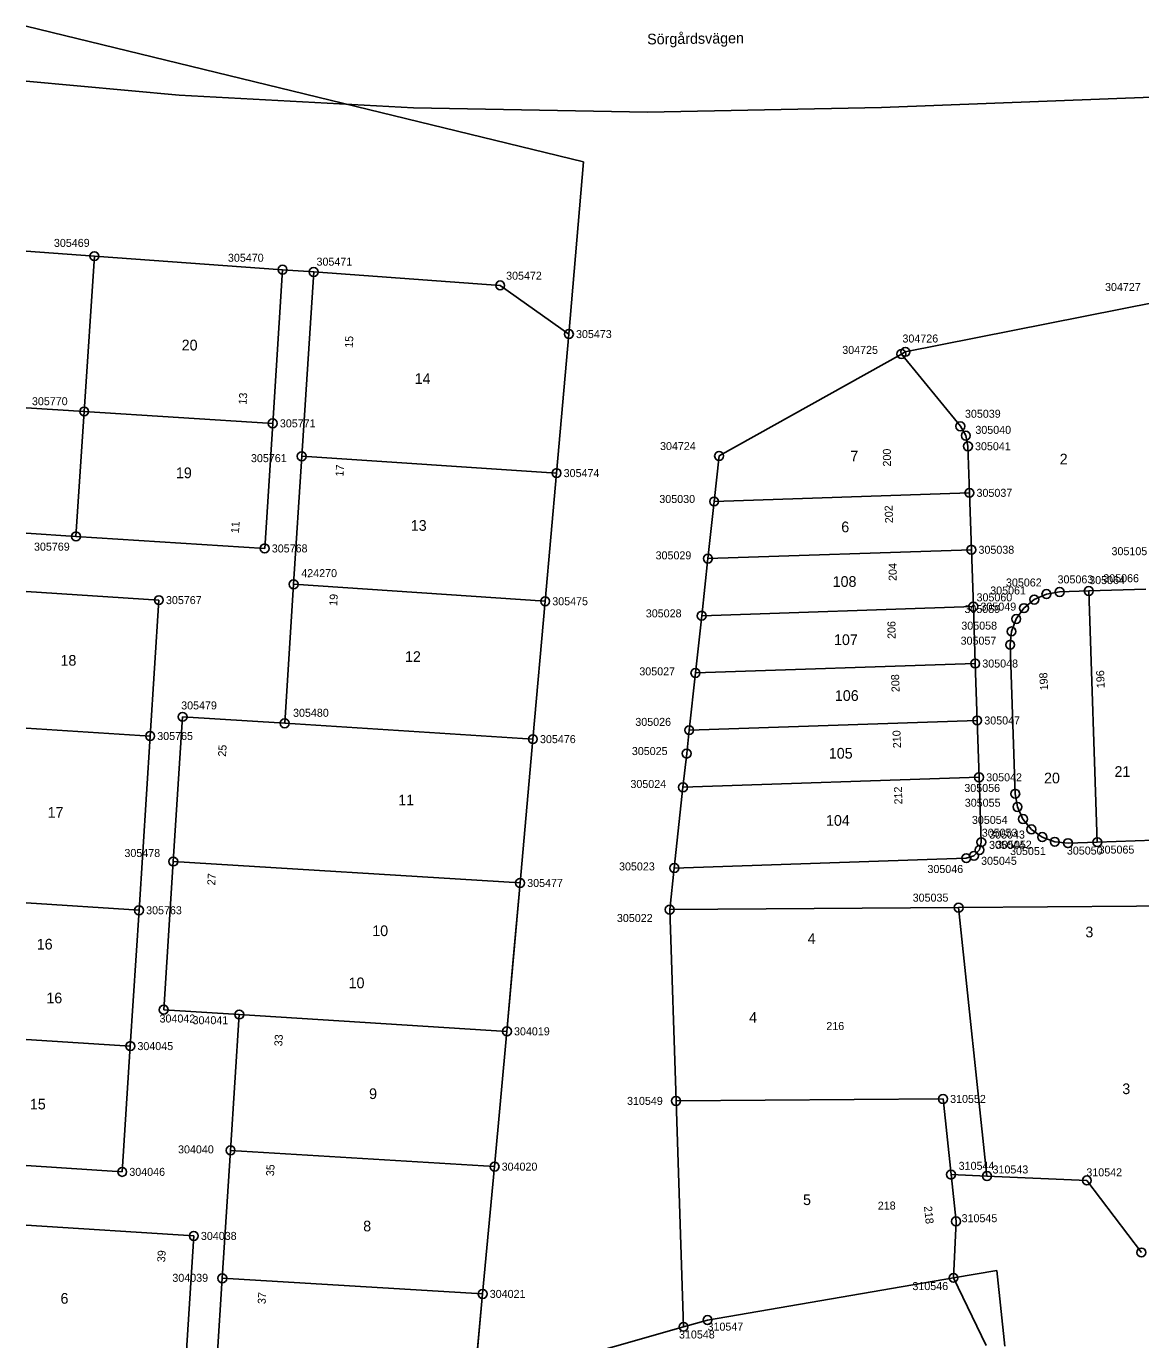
# Model space of a CAD drawing. Extents: x 141995 to 152570, y 6580184 to 6586000.
# Drawn here: x 142000 to 142125.3, y 6585201.9 to 6585349.6 of the extents above; entities that cross this region are included whole.
import ezdxf

# ---------------------------------------------------------------- set-up
doc = ezdxf.new("R2010")
doc.units = 0
for name, color, linetype in [('Level 10', 7, 'Continuous'), ('Level 13', 7, 'Continuous'), ('Level 42', 7, 'Continuous'), ('Level 5', 7, 'Continuous'), ('Level 51', 7, 'Continuous'), ('Level 53', 7, 'Continuous'), ('Level 54', 7, 'Continuous'), ('Level 55', 7, 'Continuous'), ('Level 59', 7, 'Continuous'), ('Level 6', 7, 'Continuous'), ('Level 7', 7, 'Continuous'), ('Level 8', 7, 'Continuous')]:
    doc.layers.add(name, color=color, linetype=linetype)

msp = doc.modelspace()

# ---------------------------------------------------------------- linework, layer by layer
at = {"layer": 'Level 10'}
for centre in [(142007.66, 6585323.76), (142028.82, 6585322.24), (142032.32, 6585321.98), (142053.29, 6585320.47), (142061.02, 6585315), (142098.85, 6585313), (142098.41, 6585312.76), (142006.51, 6585306.3), (142027.71, 6585304.96), (142105.04, 6585304.63), (142105.65, 6585303.58), (142030.98, 6585301.26), (142077.91, 6585301.3), (142105.89, 6585302.39), (142059.63, 6585299.37), (142106.06, 6585297.15), (142077.35, 6585296.18), (142005.59, 6585292.25), (142026.81, 6585290.9), (142106.28, 6585290.75), (142076.65, 6585289.76), (142030.06, 6585286.87), (142014.91, 6585285.09), (142058.35, 6585284.96), (142113.35, 6585285.15), (142114.72, 6585285.77), (142116.2, 6585286.01), (142119.48, 6585286.12), (142106.5, 6585284.36), (142112.19, 6585284.19), (142075.95, 6585283.33), (142111.32, 6585282.97), (142110.79, 6585281.57), (142110.64, 6585280.07), (142106.71, 6585277.96), (142075.25, 6585276.9), (142017.58, 6585271.97), (142106.93, 6585271.56), (142029.06, 6585271.24), (142074.55, 6585270.47), (142013.93, 6585269.81), (142056.97, 6585269.46), (142074.27, 6585267.84), (142107.14, 6585265.17), (142073.85, 6585264.05), (142111.21, 6585263.32), (142111.46, 6585261.84), (142112.08, 6585260.48), (142113.03, 6585259.32), (142114.25, 6585258.45), (142107.19, 6585257), (142107.39, 6585257.88), (142115.66, 6585257.92), (142117.15, 6585257.77), (142120.44, 6585257.88), (142016.53, 6585255.7), (142105.7, 6585256.08), (142106.57, 6585256.34), (142072.87, 6585254.97), (142055.53, 6585253.29), (142012.68, 6585250.22), (142072.36, 6585250.29), (142104.84, 6585250.52), (142015.46, 6585239.04), (142023.95, 6585238.5), (142054.05, 6585236.61), (142011.7, 6585234.95), (142073.07, 6585228.79), (142103.09, 6585229.01), (142022.97, 6585223.23), (142052.66, 6585221.4), (142010.79, 6585220.81), (142103.99, 6585220.51), (142108.03, 6585220.34), (142119.26, 6585219.85), (142104.55, 6585215.25), (142018.84, 6585213.61), (142125.4, 6585211.75), (142022.04, 6585208.85), (142104.27, 6585208.9), (142051.32, 6585207.09), (142076.61, 6585204.15), (142073.91, 6585203.39)]:
    msp.add_circle(centre, 0.5, dxfattribs=at)
at = {"layer": 'Level 13'}
for points in [[(142000, 6585343.44), (142017.2, 6585341.85)], [(142096.17, 6585340.46), (142170.68, 6585343.31)], [(142017.2, 6585341.85), (142043.54, 6585340.42)], [(142043.54, 6585340.42), (142069.85, 6585339.96)], [(142069.85, 6585339.96), (142096.17, 6585340.46)], [(142107.95, 6585201.31), (142104.27, 6585208.9)]]:
    msp.add_lwpolyline(points, dxfattribs=at)
at = {"layer": 'Level 5'}
for points in [[(142061.02, 6585315), (142062.68, 6585334.38)], [(142000, 6585324.31), (142007.66, 6585323.76)], [(142007.66, 6585323.76), (142028.82, 6585322.24)], [(142028.82, 6585322.24), (142032.32, 6585321.98)], [(142032.32, 6585321.98), (142053.29, 6585320.47)], [(142053.29, 6585320.47), (142061.02, 6585315)], [(142098.85, 6585313), (142127.01, 6585318.59)], [(142061.02, 6585315), (142059.63, 6585299.37)], [(142077.91, 6585301.3), (142098.41, 6585312.76)], [(142098.41, 6585312.76), (142098.85, 6585313)], [(142077.35, 6585296.18), (142077.91, 6585301.3)], [(142059.63, 6585299.37), (142058.35, 6585284.96)], [(142076.65, 6585289.76), (142077.35, 6585296.18)], [(142075.95, 6585283.33), (142076.65, 6585289.76)], [(142058.35, 6585284.96), (142056.97, 6585269.46)], [(142075.25, 6585276.9), (142075.95, 6585283.33)], [(142074.55, 6585270.47), (142075.25, 6585276.9)], [(142056.97, 6585269.46), (142055.53, 6585253.29)], [(142074.27, 6585267.84), (142074.55, 6585270.47)], [(142073.85, 6585264.05), (142074.27, 6585267.84)], [(142072.87, 6585254.97), (142073.85, 6585264.05)], [(142072.36, 6585250.29), (142072.87, 6585254.97)], [(142055.53, 6585253.29), (142054.05, 6585236.61)], [(142072.36, 6585250.29), (142073.07, 6585228.79)], [(142054.05, 6585236.61), (142052.66, 6585221.4)], [(142073.91, 6585203.39), (142073.07, 6585228.79)], [(142052.66, 6585221.4), (142051.32, 6585207.09)], [(142108.03, 6585220.34), (142103.99, 6585220.51)], [(142103.99, 6585220.51), (142104.55, 6585215.25)], [(142119.26, 6585219.85), (142108.03, 6585220.34)], [(142125.4, 6585211.75), (142119.26, 6585219.85)], [(142104.55, 6585215.25), (142104.27, 6585208.9)], [(142104.27, 6585208.9), (142076.61, 6585204.15)], [(142051.32, 6585207.09), (142050.35, 6585196.7)], [(142076.61, 6585204.15), (142073.91, 6585203.39)]]:
    msp.add_lwpolyline(points, dxfattribs=at)
at = {"layer": 'Level 6'}
for points in [[(142000, 6585181.87), (142016.42, 6585180.94), (142016.75, 6585181.04), (142020.33, 6585182.09), (142049.8, 6585190.76), (142051.32, 6585207.09), (142052.66, 6585221.4), (142054.05, 6585236.61), (142054.73, 6585244.27), (142055.53, 6585253.29), (142056.97, 6585269.46), (142058.35, 6585284.96), (142059.63, 6585299.37), (142061.02, 6585315), (142053.29, 6585320.47), (142032.32, 6585321.98), (142028.82, 6585322.24), (142007.66, 6585323.76), (142000, 6585324.31)], [(142127.01, 6585318.59), (142098.85, 6585313), (142098.41, 6585312.76), (142077.91, 6585301.3), (142077.35, 6585296.18), (142076.65, 6585289.76), (142075.95, 6585283.33), (142075.25, 6585276.9), (142074.55, 6585270.47), (142074.27, 6585267.84), (142073.85, 6585264.05), (142072.87, 6585254.97), (142072.36, 6585250.29), (142073.07, 6585228.79), (142073.91, 6585203.39), (142076.61, 6585204.15), (142104.27, 6585208.9), (142104.55, 6585215.25), (142103.99, 6585220.51), (142108.03, 6585220.34), (142119.26, 6585219.85), (142125.4, 6585211.75)]]:
    msp.add_lwpolyline(points, dxfattribs=at)
at = {"layer": 'Level 7'}
for points in [[(142006.51, 6585306.3), (142007.66, 6585323.76)], [(142028.82, 6585322.24), (142027.71, 6585304.96)], [(142030.98, 6585301.26), (142032.32, 6585321.98)], [(142098.41, 6585312.76), (142105.04, 6585304.63)], [(142000, 6585306.71), (142006.51, 6585306.3)], [(142005.59, 6585292.25), (142006.51, 6585306.3)], [(142006.51, 6585306.3), (142027.71, 6585304.96)], [(142027.71, 6585304.96), (142026.81, 6585290.9)], [(142105.04, 6585304.63), (142105.65, 6585303.58)], [(142105.65, 6585303.58), (142105.89, 6585302.39)], [(142105.89, 6585302.39), (142106.06, 6585297.15)], [(142030.06, 6585286.87), (142030.98, 6585301.26)], [(142030.98, 6585301.26), (142059.63, 6585299.37)], [(142106.06, 6585297.15), (142077.35, 6585296.18)], [(142106.06, 6585297.15), (142106.28, 6585290.75)], [(142005.59, 6585292.25), (142000, 6585292.61)], [(142026.81, 6585290.9), (142005.59, 6585292.25)], [(142106.28, 6585290.75), (142076.65, 6585289.76)], [(142106.28, 6585290.75), (142106.5, 6585284.36)], [(142029.06, 6585271.24), (142030.06, 6585286.87)], [(142030.06, 6585286.87), (142058.35, 6585284.96)], [(142000, 6585286.06), (142014.91, 6585285.09)], [(142113.35, 6585285.15), (142114.72, 6585285.77)], [(142114.72, 6585285.77), (142116.2, 6585286.01)], [(142116.2, 6585286.01), (142119.48, 6585286.12)], [(142119.48, 6585286.12), (142125.88, 6585286.34)], [(142120.44, 6585257.88), (142119.48, 6585286.12)], [(142014.91, 6585285.09), (142013.93, 6585269.81)], [(142075.95, 6585283.33), (142106.5, 6585284.36)], [(142106.5, 6585284.36), (142106.71, 6585277.96)], [(142111.32, 6585282.97), (142112.19, 6585284.19)], [(142112.19, 6585284.19), (142113.35, 6585285.15)], [(142110.79, 6585281.57), (142111.32, 6585282.97)], [(142110.64, 6585280.07), (142110.79, 6585281.57)], [(142111.21, 6585263.32), (142110.64, 6585280.07)], [(142075.25, 6585276.9), (142106.71, 6585277.96)], [(142106.71, 6585277.96), (142106.93, 6585271.56)], [(142000, 6585270.71), (142013.93, 6585269.81)], [(142016.53, 6585255.7), (142017.58, 6585271.97)], [(142017.58, 6585271.97), (142029.06, 6585271.24)], [(142029.06, 6585271.24), (142056.97, 6585269.46)], [(142074.55, 6585270.47), (142106.93, 6585271.56)], [(142106.93, 6585271.56), (142107.14, 6585265.17)], [(142013.93, 6585269.81), (142012.68, 6585250.22)], [(142073.85, 6585264.05), (142107.14, 6585265.17)], [(142107.14, 6585265.17), (142107.39, 6585257.88)], [(142111.46, 6585261.84), (142111.21, 6585263.32)], [(142112.08, 6585260.48), (142111.46, 6585261.84)], [(142113.03, 6585259.32), (142112.08, 6585260.48)], [(142114.25, 6585258.45), (142113.03, 6585259.32)], [(142107.39, 6585257.88), (142107.19, 6585257)], [(142115.66, 6585257.92), (142114.25, 6585258.45)], [(142117.15, 6585257.77), (142115.66, 6585257.92)], [(142120.44, 6585257.88), (142117.15, 6585257.77)], [(142126.84, 6585258.1), (142120.44, 6585257.88)], [(142105.7, 6585256.08), (142072.87, 6585254.97)], [(142106.57, 6585256.34), (142105.7, 6585256.08)], [(142107.19, 6585257), (142106.57, 6585256.34)], [(142016.53, 6585255.7), (142015.46, 6585239.04)], [(142016.53, 6585255.7), (142055.53, 6585253.29)], [(142000, 6585251.04), (142012.68, 6585250.22)], [(142012.68, 6585250.22), (142011.7, 6585234.95)], [(142072.36, 6585250.29), (142104.84, 6585250.52)], [(142104.84, 6585250.52), (142134.86, 6585250.74)], [(142104.84, 6585250.52), (142108.03, 6585220.34)], [(142023.95, 6585238.5), (142015.46, 6585239.04)], [(142022.97, 6585223.23), (142023.95, 6585238.5)], [(142023.95, 6585238.5), (142054.05, 6585236.61)], [(142000, 6585235.71), (142011.7, 6585234.95)], [(142011.7, 6585234.95), (142010.79, 6585220.81)], [(142103.09, 6585229.01), (142073.07, 6585228.79)], [(142103.99, 6585220.51), (142103.09, 6585229.01)], [(142022.04, 6585208.85), (142022.97, 6585223.23)], [(142022.97, 6585223.23), (142052.66, 6585221.4)], [(142010.79, 6585220.81), (142000, 6585221.52)], [(142000, 6585214.83), (142018.84, 6585213.61)], [(142018.84, 6585213.61), (142017.86, 6585198.37)], [(142020.33, 6585182.09), (142022.04, 6585208.85)], [(142022.04, 6585208.85), (142051.32, 6585207.09)]]:
    msp.add_lwpolyline(points, dxfattribs=at)
at = {"layer": 'Level 8'}
for points in [[(142000, 6585349.61), (142062.68, 6585334.38)], [(142109.14, 6585209.71), (142104.27, 6585208.9)], [(142110.03, 6585201.22), (142109.14, 6585209.71)], [(142073.91, 6585203.39), (142050.35, 6585196.7)]]:
    msp.add_lwpolyline(points, dxfattribs=at)

# ---------------------------------------------------------------- texts
at = {"layer": 'Level 42'}
msp.add_text('Sörgårdsvägen', height=1.2, rotation=0.7346, dxfattribs=at).set_placement((142069.83, 6585347.56))
at = {"layer": 'Level 51'}
for s, p in [('20', (142017.48, 6585313.16)), ('14', (142043.68, 6585309.39)), ('7', (142092.67, 6585300.69)), ('2', (142116.21, 6585300.35)), ('19', (142016.83, 6585298.8)), ('13', (142043.24, 6585292.88)), ('6', (142091.65, 6585292.72)), ('108', (142090.68, 6585286.58)), ('107', (142090.83, 6585280.04)), ('18', (142003.85, 6585277.72)), ('12', (142042.59, 6585278.14)), ('106', (142090.93, 6585273.76)), ('105', (142090.25, 6585267.27)), ('21', (142122.37, 6585265.22)), ('20', (142114.45, 6585264.49)), ('11', (142041.83, 6585262.02)), ('17', (142002.4, 6585260.63)), ('104', (142089.93, 6585259.72)), ('10', (142038.91, 6585247.32)), ('16', (142001.18, 6585245.81)), ('4', (142081.29, 6585237.57)), ('3', (142123.25, 6585229.55)), ('9', (142038.55, 6585229)), ('15', (142000.41, 6585227.83)), ('5', (142087.35, 6585217.08)), ('8', (142037.89, 6585214.12)), ('6', (142003.85, 6585205.99))]:
    msp.add_text(s, height=1.2, rotation=0.0526, dxfattribs=at).set_placement(p)
at = {"layer": 'Level 53'}
for s, p in [('305469', (142003.11, 6585324.8)), ('305470', (142022.68, 6585323.13)), ('305471', (142032.64, 6585322.69)), ('305472', (142053.96, 6585321.11)), ('304727', (142121.31, 6585319.84)), ('305473', (142061.82, 6585314.55)), ('304726', (142098.53, 6585314.05)), ('304725', (142091.76, 6585312.77)), ('305770', (142000.64, 6585307)), ('305039', (142105.56, 6585305.59)), ('305771', (142028.52, 6585304.51)), ('305040', (142106.73, 6585303.78)), ('304724', (142071.27, 6585301.96)), ('305041', (142106.69, 6585301.94)), ('305761', (142025.27, 6585300.6)), ('305474', (142060.43, 6585298.92)), ('305037', (142106.86, 6585296.7)), ('305030', (142071.19, 6585296.01)), ('305769', (142000.87, 6585290.65)), ('305768', (142027.61, 6585290.45)), ('305038', (142107.08, 6585290.3)), ('305029', (142070.77, 6585289.67)), ('305105', (142122.04, 6585290.14)), ('424270', (142030.93, 6585287.67)), ('305062', (142110.17, 6585286.62)), ('305063', (142115.97, 6585286.97)), ('305064', (142119.53, 6585286.89)), ('305066', (142121.11, 6585287.1)), ('305767', (142015.71, 6585284.64)), ('305475', (142059.15, 6585284.51)), ('305060', (142106.86, 6585284.95)), ('305061', (142108.4, 6585285.72)), ('305028', (142069.67, 6585283.15)), ('305059', (142105.5, 6585283.64)), ('305049', (142107.3, 6585283.91)), ('305058', (142105.15, 6585281.77)), ('305057', (142105.07, 6585280.08)), ('305048', (142107.51, 6585277.51)), ('305027', (142068.94, 6585276.63)), ('305479', (142017.42, 6585272.8)), ('305480', (142030, 6585271.97)), ('305047', (142107.73, 6585271.11)), ('305026', (142068.49, 6585270.95)), ('305765', (142014.73, 6585269.36)), ('305476', (142057.77, 6585269.01)), ('305025', (142068.1, 6585267.67)), ('305024', (142067.94, 6585263.97)), ('305042', (142107.95, 6585264.72)), ('305056', (142105.49, 6585263.52)), ('305055', (142105.54, 6585261.86)), ('305054', (142106.34, 6585259.93)), ('305053', (142107.45, 6585258.49)), ('305043', (142108.28, 6585258.28)), ('305044', (142108.27, 6585257.12)), ('305052', (142109.05, 6585257.15)), ('305051', (142110.63, 6585256.43)), ('305050', (142117.02, 6585256.48)), ('305065', (142120.59, 6585256.59)), ('305478', (142011.04, 6585256.21)), ('305045', (142107.37, 6585255.33)), ('305023', (142066.66, 6585254.7)), ('305046', (142101.34, 6585254.41)), ('305477', (142056.33, 6585252.84)), ('305035', (142099.68, 6585251.19)), ('305763', (142013.48, 6585249.77)), ('305022', (142066.42, 6585248.9)), ('304042', (142014.99, 6585237.6)), ('304041', (142018.7, 6585237.41)), ('304019', (142054.85, 6585236.16)), ('304045', (142012.5, 6585234.5)), ('310549', (142067.56, 6585228.34)), ('310552', (142103.89, 6585228.56)), ('304040', (142017.07, 6585222.89)), ('304020', (142053.46, 6585220.95)), ('310544', (142104.85, 6585221.04)), ('304046', (142011.59, 6585220.36)), ('310543', (142108.66, 6585220.63)), ('310542', (142119.21, 6585220.31)), ('310545', (142105.18, 6585215.15)), ('304038', (142019.64, 6585213.16)), ('304039', (142016.43, 6585208.45)), ('304021', (142052.12, 6585206.64)), ('310546', (142099.65, 6585207.52)), ('310548', (142073.4, 6585202.08)), ('310547', (142076.61, 6585202.96))]:
    msp.add_text(s, height=0.9, rotation=0.0526, dxfattribs=at).set_placement(p)
at = {"layer": 'Level 54'}
for s, rotation, p in [('15', 86.3256, (142036.7, 6585313.43)), ('13', 86.3496, (142024.77, 6585307.05)), ('200', 90.0197, (142097.23, 6585300.11)), ('17', 86.3276, (142035.66, 6585298.96)), ('202', 91.9287, (142097.48, 6585293.75)), ('11', 86.2216, (142023.91, 6585292.58)), ('204', 89.5667, (142097.87, 6585287.24)), ('19', 86.3256, (142034.96, 6585284.42)), ('206', 90.2197, (142097.75, 6585280.73)), ('208', 91.9287, (142098.21, 6585274.76)), ('198', 93.1658, (142114.91, 6585274.97)), ('196', 91.9437, (142121.27, 6585275.21)), ('210', 91.9287, (142098.37, 6585268.46)), ('25', 86.2646, (142022.45, 6585267.47)), ('212', 91.3827, (142098.52, 6585262.13)), ('27', 86.3446, (142021.24, 6585253.01)), ('216', 0.3596, (142089.97, 6585236.75)), ('33', 86.3256, (142028.78, 6585234.91)), ('35', 86.3476, (142027.85, 6585220.3)), ('218', 0.6246, (142095.76, 6585216.56)), ('39', 86.3256, (142015.61, 6585210.63)), ('37', 86.3276, (142026.91, 6585205.92))]:
    msp.add_text(s, height=0.9, rotation=rotation, dxfattribs=at).set_placement(p)
at = {"layer": 'Level 55'}
msp.add_text('218', height=0.9, rotation=276.0329, dxfattribs=at).set_placement((142100.95, 6585216.92))
at = {"layer": 'Level 59'}
for s, p in [('3', (142119.1, 6585247.18)), ('4', (142087.87, 6585246.44)), ('10', (142036.25, 6585241.46)), ('16', (142002.26, 6585239.76))]:
    msp.add_text(s, height=1.2, rotation=0.0526, dxfattribs=at).set_placement(p)

doc.saveas('drawing.dxf')
